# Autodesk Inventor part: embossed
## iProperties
Shininess: 64.0
Length Units: 11269
Angle Units: 11279
Time Units: 11290
Mass Units: 11283
Length Display Precision: 3
Angle Display Precision: 2
Compacted: True
Part Number: embossed
Document SubType Name: Modeling
Created: 2002-12
Designer: deepak
Density: 0.0
Volumn: 0.0
Area: 0.0
PropertySet Name: Model Information
Control State: 0
Master: False
Checked Out: False
Author: deepak
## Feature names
1. Extrusion1
2. Extrusion2
